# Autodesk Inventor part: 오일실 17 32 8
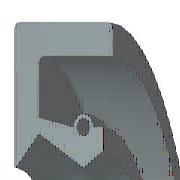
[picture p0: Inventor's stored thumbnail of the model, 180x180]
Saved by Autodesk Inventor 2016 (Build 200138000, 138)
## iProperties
IsCustomPart: 1
Created: 2012-02
Part Number: 오일실 17 32 8
Material: 고무
Description: 오일-실
Document SubType Name: Modeling
Standard: KS B 2804
Designer: mduedu
Standards Organization: KS
Language: ko-KR
Size Designation: D - 17 32 8
Categories: <MemberInstance><Categories><Category DisplayName="샤프트 부품" InternalName="7f7aeb1f-a693-4053-b835-cee3144e0d98" Mnemonic="SHFT"><Category DisplayName="실링" Intern
Density: 0.93 g/cm^3
Appearance: 고무 - 검은색 - 버전 1.1
Mass: 2.28027 g
Surface Area: 32.1224 cm^2
Volume: 2.45191 cm^3
Author: mduedu
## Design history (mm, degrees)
revolve "본체" stored, may be unused: angle "d17" = 90 deg
revolve "스프링1" stored, may be unused: angle "d18" = 90 deg
body "Solid1"
sketch "스케치1"
  geometry: L1 (0, 16)-(8, 16); L2 (8, 14.25)-(1.75, 14.25); L3 (1.75, 10.25)-(4.9, 8.5); L4 (4.9, 8.5)-(0, 8.5); L5 (0, 0)-(9.586, 0) reference; L6 (4.9, 8.5)-(6.3, 9.375); L7 (0, 18)-(0, -3) reference; L8 (-1.941, 0)-(11.507, 0) reference; L9 (4.2, 10.6)-(1.75, 11.21); L10 (1.75, 11.21)-(1.75, 14.25); L11 (0, 16)-(0, 8.588); L12 (4.9, 8.5)-(0, 8.5); L13 (1.75, 10.25)-(0.152, 8.528); L14 (8, 16)-(8, 14.25); L15 (5.6, 10.6)-(6.3, 10.6); L16 (6.3, 10.6)-(6.3, 9.375); C1 r 0.455 at (4.9, 10.6); A1 r 0.7 centre (4.9, 10.6) between (5.6, 10.6) and (4.2, 10.6); A2 r 0.088 centre (0.088, 8.588) between (0, 8.588) and (0.152, 8.528); 1 further point
  constraints: 28 end point, 5 horizontal alignment, 5 point on line, 4 point on circle, 4 vertical alignment, 3 centre point, 3 tangent, 2 collinear, 2 horizontal, 2 perpendicular, 1 coincident, 1 parallel
  dimensions: "d0" = 32 diameter of L1 L5 (= SD2); "d1" = 1.75 distance of L1.end L2.start (= SD); "d2" = 0.91 diameter of C1 (= SPDI); "d3" = 1.4 diameter of A1 (= SPDA); "d4" = 17 diameter of L3.end L5 (= NND); "d5" = 20.5 diameter of L3.start L5 (= TKDM); "d7" = 22.42 diameter of L9.end L5 (= TKDM + 0.24 x SWDT); "d8" = 1.75 distance between parallel lines of L11 L10 (= SD); "d9" = 4.9 distance from line of L11 C1.centre (= SPDST); "d10" = 21.2 diameter of C1.centre L5 (= HLDM); "d11" = 0.0875 radius of A2 (= 0.25 x LAB); "d12" = 6.3 distance between parallel lines of L11 L16 (= SDI); "d13" = 18.75 diameter of L6.end L5 (= ABDM); "d14" = 8 distance from line of L11 L1.end (= SWDT)
fillet "모깎기1" dims "d6" = 0.3 (= RR)
other parameters: "SD2" = 32 [user parameter; used in 1 equation term], "SWDT" = 8 [user parameter; used in 2 equation terms], "RR" = 0.3 [user parameter; used in 1 equation term], "SD" = 1.75 [user parameter; used in 2 equation terms], "NND" = 17 [user parameter; used in 1 equation term], "SPDA" = 1.4 [user parameter; used in 1 equation term], "SPDI" = 0.91 [user parameter; used in 1 equation term], "TKDM" = 20.5 [user parameter; used in 2 equation terms], "HLDM" = 21.2 [user parameter; used in 1 equation term], "ABDM" = 18.75 [user parameter; used in 1 equation term], "SDI" = 6.3 [user parameter; used in 1 equation term], "SPDST" = 4.9 [user parameter; used in 1 equation term], "LAB" = 0.35 [user parameter; used in 1 equation term], "d15" = 0, "d16" = 0, "d19" = 0
